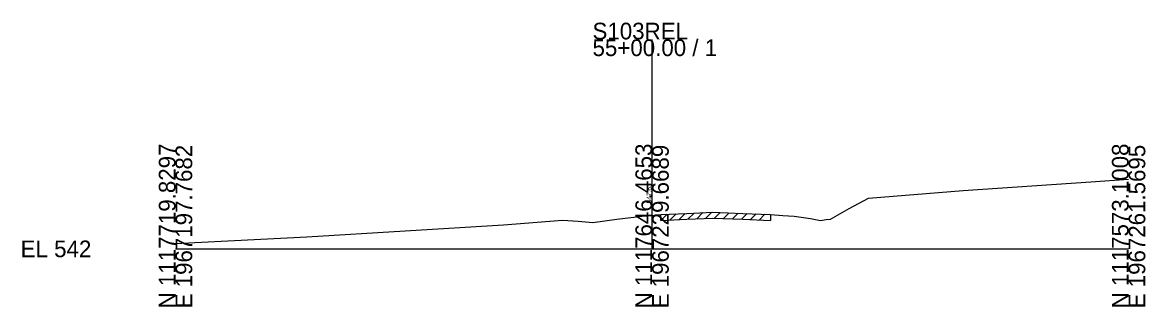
# Model space of a CAD drawing. Extents: x -26 to 163, y -10 to 24518.
# Drawn here: x -25.7 to 162.8, y 5490.3 to 5538 of the extents above; entities that cross this region are included whole.
import ezdxf

# ---------------------------------------------------------------- set-up
doc = ezdxf.new("R2010")
doc.units = 0
for name, color, linetype in [('RD_GPK_XS_Cell', 7, 'Continuous'), ('RD_XS_ExGround', 7, 'Continuous'), ('RD_XS_ExPaveRet', 7, 'Continuous'), ('RD_XS_TX_Elev_EX', 7, 'Continuous')]:
    doc.layers.add(name, color=color, linetype=linetype)

msp = doc.modelspace()

# ---------------------------------------------------------------- linework, layer by layer
at = {"layer": 'RD_GPK_XS_Cell'}
for p, q in [((80, 5500), (80, 5535.19)), ((0, 5500), (80, 5500)), ((80, 5500), (160, 5500))]:
    msp.add_line(p, q, dxfattribs=at)
at = {"layer": 'RD_XS_ExGround'}
msp.add_lwpolyline([(0, 5500.92), (1.06, 5500.96), (22.07, 5502.02), (55.06, 5504.06), (64.96, 5504.83), (67.57, 5504.63), (70.07, 5504.44), (74.06, 5504.96), (78.33, 5505.47), (80, 5505.63), (81.49, 5505.76), (85.82, 5505.96), (90.21, 5506.16), (95.21, 5505.96), (99.86, 5505.76), (101.94, 5505.63), (103.83, 5505.49), (106.61, 5505.08), (108.25, 5504.76), (109.24, 5504.91), (109.98, 5505.01), (113.08, 5506.8), (116.33, 5508.51), (132.25, 5509.82), (153.63, 5511.28), (160, 5511.73)], dxfattribs=at)
at = {"layer": 'RD_XS_ExPaveRet'}
for p, q in [((81.49, 5504.76), (82.54, 5505.81)), ((81.49, 5504.76), (81.49, 5505.76)), ((82.99, 5504.83), (84.04, 5505.88)), ((84.49, 5504.9), (85.54, 5505.95)), ((85.82, 5504.96), (90.21, 5505.16)), ((85.99, 5504.97), (87.04, 5506.02)), ((87.49, 5505.04), (88.54, 5506.09)), ((88.99, 5505.11), (90.04, 5506.16)), ((90.21, 5505.16), (95.21, 5504.96)), ((90.49, 5505.15), (91.45, 5506.11)), ((91.99, 5505.09), (92.95, 5506.05)), ((93.49, 5505.03), (94.45, 5505.99)), ((94.99, 5504.97), (95.95, 5505.92)), ((96.49, 5504.9), (97.45, 5505.86)), ((98, 5504.84), (98.95, 5505.8)), ((99.86, 5505.76), (99.86, 5504.76)), ((81.49, 5504.76), (85.82, 5504.96)), ((95.21, 5504.96), (99.86, 5504.76))]:
    msp.add_line(p, q, dxfattribs=at)

# ---------------------------------------------------------------- texts
at = {"layer": 'RD_GPK_XS_Cell'}
for s, p in [('S103REL', (70, 5535.19)), ('55+00.00 / 1', (70, 5532.39)), ('EL 542', (-26, 5498.6))]:
    msp.add_text(s, height=2.8, dxfattribs=at).set_placement(p)
for s, p in [('N 1117719.8297', (0, 5490)), ('E 1967197.7682', (2.8, 5490)), ('N 1117646.4653', (80, 5490)), ('E 1967229.6689', (82.8, 5490)), ('N 1117573.1008', (160, 5490)), ('E 1967261.5695', (162.8, 5490))]:
    msp.add_text(s, height=2.8, rotation=90, dxfattribs=at).set_placement(p)
at = {"layer": 'RD_XS_TX_Elev_EX'}
msp.add_text('547.63', height=0.8, rotation=90, dxfattribs=at).set_placement((79.9, 5507.63))

doc.saveas('drawing.dxf')
